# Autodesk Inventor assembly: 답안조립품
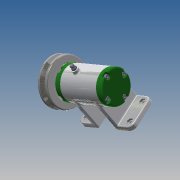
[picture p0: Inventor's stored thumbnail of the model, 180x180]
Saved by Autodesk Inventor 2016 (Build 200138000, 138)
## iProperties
Created: 2017-02
Part Number: 답안조립품
Document SubType Name: Assembly
Designer: Administrator
Author: Administrator
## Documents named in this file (14)
- D:\470208V1014\답안조립품.iam
- D:\470208V1014\부품1.ipt
- D:\470208V1014\앞커버.ipt
- D:\470208V1014\뒤커버.ipt
- D:\470208V1014\축.ipt
- D:\470208V1014\베어링 15 x 32 x 9.ipt
- D:\470208V1014\키 3 x 3 x 12.ipt
- D:\470208V1014\V벨트풀리.ipt
- D:\470208V1014\와셔 8x17.ipt
- D:\470208V1014\스프링와셔 8.ipt
- D:\470208V1014\너트 M 8.ipt
- D:\470208V1014\볼트 M4 x 12.ipt
- D:\470208V1014\니플 M 6 x 0.75.ipt
- D:\470208V1014\오일 실 15 25 7.ipt
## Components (11 placed, 3 different names)
1. KS B 2023 6002 - 15 x 32 x 9:1
2. KS B 2023 6002 - 15 x 32 x 9:2
3. V벨트풀리:1 — 각도:1
4. ISO 4762 M4 x 12:1
5. ISO 4762 M4 x 12:2
6. ISO 4762 M4 x 12:3
7. ISO 4762 M4 x 12:4
8. ISO 4762 M4 x 12:5
9. ISO 4762 M4 x 12:6
10. ISO 4762 M4 x 12:7
11. ISO 4762 M4 x 12:8
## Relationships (1: Angle 1)
- 각도:1 [Angle]: V벨트풀리:1
